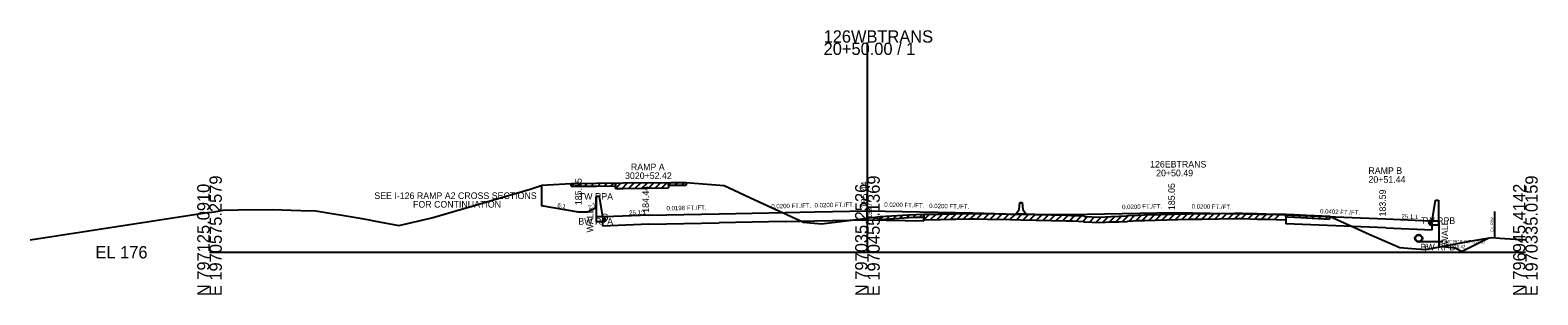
# Model space of a CAD drawing. Extents: x -6494 to 1970605, y -10 to 798140.
# Drawn here: x 959.1 to 1302.8, y 2990.3 to 3050.6 of the extents above; entities that cross this region are included whole.
import ezdxf

# ---------------------------------------------------------------- set-up
doc = ezdxf.new("R2010")
doc.units = 0
for name, color, linetype in [('Default', 7, 'Continuous'), ('RD_EX_SU_Misc_TxCode', 7, 'Continuous'), ('RD_GPK_XS_Cell', 7, 'Continuous'), ('RD_Sketch1', 7, 'Continuous'), ('RD_XS_Base', 7, 'Continuous'), ('RD_XS_Box', 7, 'Continuous'), ('RD_XS_EwShp', 7, 'Continuous'), ('RD_XS_ExGround', 7, 'Continuous'), ('RD_XS_ExPaveRet', 7, 'Continuous'), ('RD_XS_ExRW', 7, 'Continuous'), ('RD_XS_MedBWall', 7, 'Continuous'), ('RD_XS_Misc_Line', 7, 'Continuous'), ('RD_XS_Pave', 7, 'Continuous'), ('RD_XS_PaveOvlay', 7, 'Continuous'), ('RD_XS_PaveShd', 7, 'Continuous'), ('RD_XS_Pipe', 7, 'Continuous'), ('RD_XS_TieSlope', 7, 'Continuous'), ('RD_XS_TX_Elev_EX', 7, 'Continuous'), ('RD_XS_TX_Elev_PR', 7, 'Continuous'), ('RD_XS_TX_Misc', 7, 'Continuous'), ('RD_XS_TX_Notes', 7, 'Continuous'), ('RD_XS_TX_Profile', 7, 'Continuous'), ('RD_XS_TX_Slope', 7, 'Continuous'), ('RD_XS_TX_Station', 7, 'Continuous')]:
    doc.layers.add(name, color=color, linetype=linetype)

msp = doc.modelspace()

# ---------------------------------------------------------------- linework, layer by layer
at = {"layer": 'Default'}
for p, q in [((1184.58, 3009.76), (1184.75, 3011.34)), ((1184.75, 3011.34), (1185.25, 3011.34)), ((1185.25, 3011.34), (1185.42, 3009.76)), ((1184, 3008.92), (1184.58, 3009.76)), ((1184, 3008.67), (1184, 3008.92)), ((1186, 3008.67), (1184, 3008.67)), ((1185.42, 3009.76), (1186, 3008.92)), ((1186, 3008.92), (1186, 3008.67))]:
    msp.add_line(p, q, dxfattribs=at)
at = {"layer": 'RD_GPK_XS_Cell'}
for p, q in [((1150, 3000), (1150, 3047.74)), ((1000, 3000), (1150, 3000)), ((1150, 3000), (1300, 3000))]:
    msp.add_line(p, q, dxfattribs=at)
at = {"layer": 'RD_XS_Base'}
for p, q in [((1090.15, 3007.48), (1090.15, 3008.04)), ((1089.65, 3007.46), (1090.15, 3007.48)), ((1089.65, 3005.98), (1089.65, 3007.46)), ((1100.18, 3006.4), (1089.65, 3005.98)), ((1100.18, 3006.4), (1116.23, 3006.72)), ((1131.27, 3007.02), (1116.23, 3006.72)), ((1131.27, 3007.02), (1138, 3007.16)), ((1138, 3007.16), (1150, 3007.4)), ((1150, 3007.4), (1162.89, 3007.14)), ((1268.18, 3005.55), (1245.36, 3006.47)), ((1268.18, 3005.55), (1278.72, 3005.13)), ((1278.22, 3006.63), (1278.22, 3007.19)), ((1278.72, 3006.61), (1278.22, 3006.63)), ((1278.72, 3005.13), (1278.72, 3006.61))]:
    msp.add_line(p, q, dxfattribs=at)
at = {"layer": 'RD_XS_Box'}
for p, q in [((1088.15, 3010.22), (1088.15, 3008.04)), ((1090.15, 3008.04), (1088.15, 3008.04)), ((1278.22, 3007.19), (1280.23, 3007.19)), ((1280.23, 3007.19), (1280.23, 3001.18))]:
    msp.add_line(p, q, dxfattribs=at)
at = {"layer": 'RD_XS_ExGround'}
msp.add_line((1000, 3009.07), (959.11, 3002.75), dxfattribs=at)
msp.add_lwpolyline([(1000, 3009.07), (1001.06, 3009.23), (1003.09, 3009.6), (1006.52, 3009.65), (1014.26, 3009.73), (1020.8, 3009.53), (1024.25, 3009.42), (1033.88, 3007.83), (1036.39, 3007.39), (1037.48, 3007.18), (1043.18, 3006.13), (1050.69, 3007.85), (1073.12, 3014.35), (1075.82, 3015.3), (1077.09, 3015.37), (1082.48, 3015.65), (1084.28, 3015.67), (1088.23, 3015.7), (1094.32, 3015.78), (1105.19, 3015.91), (1107.73, 3015.91), (1108.67, 3015.91), (1110.58, 3015.75), (1117.31, 3015.18), (1124.29, 3011.97), (1135.39, 3006.86), (1137.03, 3006.7), (1139.5, 3006.48), (1150, 3007.77), (1150.38, 3007.82), (1152.88, 3008.11), (1159.39, 3008.52), (1161.11, 3008.62), (1166.64, 3008.71), (1169.08, 3008.75), (1170.16, 3008.78), (1173.1, 3008.86), (1174.57, 3008.84), (1177.35, 3008.79), (1182.55, 3008.7), (1184.98, 3008.65), (1195.28, 3008.44), (1196.46, 3008.41), (1196.79, 3008.4), (1199.26, 3008.28), (1199.49, 3008.18), (1202.92, 3008.03), (1205.59, 3008.15), (1207.4, 3008.21), (1209.15, 3008.27), (1209.45, 3008.35), (1211.78, 3008.45), (1213.18, 3008.49), (1223.34, 3008.77), (1226.24, 3008.81), (1230.18, 3008.85), (1233.77, 3008.92), (1234.87, 3008.94), (1235.5, 3008.92), (1238.91, 3008.81), (1240.93, 3008.76), (1247.31, 3008.62), (1250.09, 3008.48), (1255.36, 3008.19), (1264.38, 3004.1), (1271.37, 3001.05), (1274.01, 3000.84), (1277.2, 3000.61), (1285.34, 3002.15), (1286.96, 3002.46), (1290.46, 3003.04), (1292.29, 3003.33), (1294.2, 3003.2), (1300, 3002.8)], dxfattribs=at)
at = {"layer": 'RD_XS_ExPaveRet'}
for p, q in [((1082.48, 3015.02), (1082.48, 3015.65)), ((1082.48, 3015.02), (1084.28, 3015.04)), ((1084.28, 3015.04), (1088.23, 3015.08)), ((1088.23, 3015.08), (1092.54, 3015.13)), ((1092.54, 3014.51), (1092.54, 3015.76)), ((1092.54, 3015.76), (1092.54, 3015.13)), ((1094.32, 3014.53), (1104.65, 3014.66)), ((1104.65, 3015.91), (1104.65, 3014.66)), ((1104.65, 3015.28), (1104.65, 3015.91)), ((1104.65, 3015.28), (1105.19, 3015.29)), ((1105.19, 3015.29), (1107.73, 3015.28)), ((1107.73, 3015.28), (1108.67, 3015.28)), ((1108.67, 3015.91), (1108.67, 3015.28)), ((1092.54, 3014.51), (1094.32, 3014.53)), ((1152.88, 3007.49), (1152.88, 3008.11)), ((1152.88, 3007.49), (1159.39, 3007.89)), ((1159.39, 3007.89), (1161.11, 3008)), ((1161.11, 3008), (1162.89, 3008.03)), ((1162.89, 3007.4), (1162.89, 3008.65)), ((1162.89, 3008.65), (1162.89, 3008.03)), ((1230.18, 3007.6), (1233.77, 3007.67)), ((1233.77, 3007.67), (1234.87, 3007.69)), ((1234.87, 3007.69), (1235.5, 3007.67)), ((1235.5, 3007.67), (1238.91, 3007.56)), ((1245.36, 3008.66), (1245.36, 3007.41)), ((1245.36, 3008.04), (1245.36, 3008.66)), ((1245.36, 3008.04), (1247.31, 3007.99)), ((1247.31, 3007.99), (1250.09, 3007.85)), ((1250.09, 3007.85), (1255.36, 3007.57)), ((1255.36, 3008.19), (1255.36, 3007.57)), ((1162.89, 3007.4), (1166.64, 3007.46)), ((1166.64, 3007.46), (1169.08, 3007.5)), ((1169.08, 3007.5), (1170.16, 3007.53)), ((1170.16, 3007.53), (1173.1, 3007.61)), ((1173.1, 3007.61), (1174.57, 3007.59)), ((1174.57, 3007.59), (1177.35, 3007.54)), ((1177.35, 3007.54), (1182.55, 3007.45)), ((1182.55, 3007.45), (1184.98, 3007.4)), ((1184.98, 3007.4), (1195.28, 3007.19)), ((1195.28, 3007.19), (1196.46, 3007.16)), ((1196.46, 3007.16), (1196.79, 3007.15)), ((1196.79, 3007.15), (1199.26, 3007.03)), ((1199.26, 3007.03), (1199.49, 3006.93)), ((1199.49, 3006.93), (1202.92, 3006.78)), ((1202.92, 3006.78), (1205.59, 3006.9)), ((1205.59, 3006.9), (1207.4, 3006.96)), ((1207.4, 3006.96), (1209.15, 3007.02)), ((1209.15, 3007.02), (1209.45, 3007.1)), ((1209.45, 3007.1), (1211.78, 3007.2)), ((1211.78, 3007.2), (1213.18, 3007.24)), ((1213.18, 3007.24), (1223.34, 3007.52)), ((1223.34, 3007.52), (1226.24, 3007.56)), ((1226.24, 3007.56), (1230.18, 3007.6)), ((1238.91, 3007.56), (1240.93, 3007.51)), ((1240.93, 3007.51), (1245.36, 3007.41))]:
    msp.add_line(p, q, dxfattribs=at)
at = {"layer": 'RD_XS_ExRW'}
msp.add_line((1292.97, 3009.29), (1292.97, 3003.29), dxfattribs=at)
at = {"layer": 'RD_XS_MedBWall'}
for p, q in [((1088.9, 3012.71), (1088.15, 3012.71)), ((1088.15, 3012.71), (1088.15, 3007.04)), ((1088.15, 3010.22), (1088.15, 3012.71)), ((1089.65, 3008.04), (1088.9, 3012.71)), ((1278.72, 3007.19), (1279.47, 3011.85)), ((1279.47, 3011.85), (1280.22, 3011.85)), ((1280.22, 3011.85), (1280.22, 3006.19)), ((1090.15, 3008.04), (1089.65, 3008.04)), ((1090.15, 3007.04), (1090.15, 3008.04)), ((1088.15, 3007.04), (1090.15, 3007.04)), ((1278.22, 3006.19), (1278.22, 3007.19)), ((1278.22, 3007.19), (1278.72, 3007.19)), ((1280.22, 3006.19), (1278.22, 3006.19))]:
    msp.add_line(p, q, dxfattribs=at)
at = {"layer": 'RD_XS_Misc_Line'}
for p, q in [((1082.48, 3015.02), (1083.12, 3015.65)), ((1083.99, 3015.04), (1084.63, 3015.67)), ((1085.5, 3015.05), (1086.13, 3015.68)), ((1087.01, 3015.07), (1087.64, 3015.7)), ((1088.52, 3015.08), (1089.15, 3015.71)), ((1090.02, 3015.1), (1090.66, 3015.73)), ((1091.53, 3015.12), (1092.17, 3015.75)), ((1092.54, 3014.51), (1093.81, 3015.77)), ((1094.05, 3014.52), (1095.32, 3015.79)), ((1095.55, 3014.54), (1096.83, 3015.81)), ((1097.06, 3014.56), (1098.34, 3015.83)), ((1098.57, 3014.58), (1099.84, 3015.85)), ((1100.08, 3014.6), (1101.35, 3015.87)), ((1101.59, 3014.62), (1102.86, 3015.88)), ((1103.1, 3014.64), (1104.37, 3015.9)), ((1104.65, 3015.28), (1105.28, 3015.91)), ((1106.16, 3015.29), (1106.78, 3015.91)), ((1107.67, 3015.28), (1108.29, 3015.91)), ((1152.88, 3007.49), (1153.56, 3008.15)), ((1154.39, 3007.58), (1155.06, 3008.25)), ((1155.9, 3007.67), (1156.57, 3008.34)), ((1157.41, 3007.77), (1158.08, 3008.43)), ((1158.92, 3007.86), (1159.59, 3008.53)), ((1160.43, 3007.95), (1161.09, 3008.62)), ((1161.93, 3008.01), (1162.57, 3008.65)), ((1162.89, 3007.4), (1164.16, 3008.67)), ((1164.39, 3007.43), (1165.67, 3008.7)), ((1165.9, 3007.45), (1167.18, 3008.72)), ((1167.41, 3007.48), (1168.69, 3008.75)), ((1168.92, 3007.5), (1170.21, 3008.78)), ((1170.43, 3007.54), (1171.72, 3008.82)), ((1171.93, 3007.58), (1173.22, 3008.86)), ((1173.44, 3007.6), (1174.68, 3008.84)), ((1174.95, 3007.58), (1176.19, 3008.81)), ((1176.46, 3007.56), (1177.69, 3008.78)), ((1177.97, 3007.53), (1179.2, 3008.76)), ((1179.48, 3007.5), (1180.71, 3008.73)), ((1180.98, 3007.48), (1182.22, 3008.71)), ((1182.49, 3007.45), (1183.72, 3008.68)), ((1184, 3007.42), (1185.23, 3008.65)), ((1185.51, 3007.39), (1186.74, 3008.62)), ((1187.02, 3007.36), (1188.25, 3008.58)), ((1188.52, 3007.33), (1189.76, 3008.55)), ((1190.03, 3007.3), (1191.26, 3008.52)), ((1191.54, 3007.27), (1192.77, 3008.49)), ((1193.05, 3007.23), (1194.28, 3008.46)), ((1194.56, 3007.2), (1195.79, 3008.43)), ((1196.07, 3007.17), (1197.28, 3008.37)), ((1197.57, 3007.11), (1198.77, 3008.3)), ((1199.08, 3007.03), (1200.2, 3008.15)), ((1200.59, 3006.88), (1201.79, 3008.08)), ((1202.1, 3006.81), (1203.34, 3008.04)), ((1203.61, 3006.81), (1204.92, 3008.12)), ((1205.11, 3006.88), (1206.42, 3008.18)), ((1206.62, 3006.93), (1207.92, 3008.23)), ((1208.13, 3006.98), (1209.51, 3008.36)), ((1209.64, 3007.11), (1210.95, 3008.42)), ((1211.15, 3007.17), (1212.45, 3008.47)), ((1212.66, 3007.23), (1213.95, 3008.51)), ((1214.16, 3007.27), (1215.46, 3008.55)), ((1215.67, 3007.31), (1216.97, 3008.6)), ((1217.18, 3007.35), (1218.47, 3008.64)), ((1218.69, 3007.39), (1219.98, 3008.68)), ((1220.2, 3007.44), (1221.49, 3008.72)), ((1221.7, 3007.48), (1223, 3008.76)), ((1223.21, 3007.52), (1224.49, 3008.79)), ((1224.72, 3007.54), (1226, 3008.81)), ((1226.23, 3007.56), (1227.5, 3008.83)), ((1227.74, 3007.58), (1229.01, 3008.84)), ((1229.25, 3007.59), (1230.52, 3008.86)), ((1230.75, 3007.61), (1232.04, 3008.89)), ((1232.26, 3007.64), (1233.54, 3008.92)), ((1233.77, 3007.67), (1235.04, 3008.94)), ((1235.28, 3007.68), (1236.5, 3008.89)), ((1236.79, 3007.63), (1238.01, 3008.84)), ((1238.3, 3007.58), (1239.52, 3008.8)), ((1239.8, 3007.54), (1241.03, 3008.76)), ((1241.31, 3007.51), (1242.54, 3008.73)), ((1242.82, 3007.47), (1244.05, 3008.69)), ((1245.36, 3008.04), (1245.97, 3008.65)), ((1246.87, 3008), (1247.48, 3008.61)), ((1248.37, 3007.94), (1248.97, 3008.53)), ((1249.88, 3007.86), (1250.48, 3008.46)), ((1251.39, 3007.78), (1251.99, 3008.38)), ((1252.9, 3007.7), (1253.5, 3008.29)), ((1254.41, 3007.62), (1255, 3008.21))]:
    msp.add_line(p, q, dxfattribs=at)
at = {"layer": 'RD_XS_Pave'}
for p, q in [((1100.18, 3008.44), (1116.23, 3008.76)), ((1131.27, 3009.06), (1138, 3009.2)), ((1138, 3009.2), (1150, 3009.44)), ((1150, 3009.44), (1174, 3008.96)), ((1196.09, 3008.57), (1220.09, 3009.05)), ((1220.09, 3009.05), (1232.09, 3008.81)), ((1232.09, 3008.81), (1243.24, 3008.59)), ((1243.24, 3008.59), (1268.18, 3007.59))]:
    msp.add_line(p, q, dxfattribs=at)
at = {"layer": 'RD_XS_PaveOvlay'}
for p, q in [((1162.89, 3008.65), (1166.64, 3008.71)), ((1162.89, 3008.65), (1162.89, 3007.14)), ((1166.64, 3008.71), (1169.08, 3008.75)), ((1169.08, 3008.75), (1170.16, 3008.78)), ((1170.16, 3008.78), (1173.1, 3008.86)), ((1173.1, 3008.86), (1174.57, 3008.84)), ((1174.57, 3008.84), (1177.35, 3008.79)), ((1177.35, 3008.79), (1182.55, 3008.7)), ((1182.55, 3008.7), (1184.98, 3008.65)), ((1184.98, 3008.65), (1195.28, 3008.44)), ((1195.28, 3008.44), (1196.46, 3008.41)), ((1196.46, 3008.41), (1196.79, 3008.4)), ((1196.79, 3008.4), (1199.26, 3008.28)), ((1199.26, 3008.28), (1199.49, 3008.18)), ((1199.49, 3008.18), (1202.92, 3008.03)), ((1202.92, 3008.03), (1205.59, 3008.15)), ((1205.59, 3008.15), (1207.4, 3008.21)), ((1207.4, 3008.21), (1209.15, 3008.27)), ((1209.15, 3008.27), (1209.45, 3008.35)), ((1209.45, 3008.35), (1211.78, 3008.45)), ((1211.78, 3008.45), (1213.18, 3008.49)), ((1213.18, 3008.49), (1223.34, 3008.77)), ((1223.34, 3008.77), (1226.24, 3008.81)), ((1226.24, 3008.81), (1230.18, 3008.85)), ((1230.18, 3008.85), (1233.77, 3008.92)), ((1233.77, 3008.92), (1234.87, 3008.94)), ((1234.87, 3008.94), (1235.5, 3008.92)), ((1235.5, 3008.92), (1238.91, 3008.81)), ((1238.91, 3008.81), (1240.93, 3008.76)), ((1240.93, 3008.76), (1245.36, 3008.66)), ((1245.36, 3008.66), (1245.36, 3006.47))]:
    msp.add_line(p, q, dxfattribs=at)
at = {"layer": 'RD_XS_PaveShd'}
for p, q in [((1100.18, 3008.44), (1090.15, 3008.04)), ((1116.23, 3008.76), (1131.27, 3009.06)), ((1174, 3008.96), (1184, 3008.67)), ((1192.35, 3008.5), (1184, 3008.67)), ((1196.09, 3008.57), (1192.35, 3008.5)), ((1268.18, 3007.59), (1278.22, 3007.19))]:
    msp.add_line(p, q, dxfattribs=at)
at = {"layer": 'RD_XS_Pipe'}
msp.add_line((1276.17, 3002.42), (1281.17, 3002.42), dxfattribs=at)
for radius in [0.85, 0.75]:
    msp.add_circle((1275.67, 3003.17), radius, dxfattribs=at)
at = {"layer": 'RD_XS_TieSlope'}
for p, q in [((1075.69, 3015.26), (1075.69, 3010.56)), ((1084.15, 3009.15), (1075.69, 3010.56)), ((1086.15, 3009.15), (1084.15, 3009.15)), ((1088.15, 3010.15), (1086.15, 3009.15)), ((1280.23, 3001.38), (1284, 3001.01)), ((1284, 3001.01), (1285.62, 3000.2)), ((1291.69, 3003.24), (1285.62, 3000.2))]:
    msp.add_line(p, q, dxfattribs=at)

# ---------------------------------------------------------------- texts
at = {"layer": 'RD_EX_SU_Misc_TxCode'}
msp.add_text('G', height=1.5, dxfattribs=at).set_placement((1089.4, 3007.29))
at = {"layer": 'RD_GPK_XS_Cell'}
for s, p in [('126WBTRANS', (1140, 3047.74)), ('20+50.00 / 1', (1140, 3044.94)), ('EL 176', (974, 2998.6))]:
    msp.add_text(s, height=2.8, dxfattribs=at).set_placement(p)
for s, p in [('N 797125.0910', (1000, 2990)), ('E 1970575.2579', (1002.8, 2990)), ('N 797035.2526', (1150, 2990)), ('E 1970455.1369', (1152.8, 2990)), ('N 796945.4142', (1300, 2990)), ('E 1970335.0159', (1302.8, 2990))]:
    msp.add_text(s, height=2.8, rotation=90, dxfattribs=at).set_placement(p)
at = {"layer": 'RD_Sketch1'}
msp.add_text('T', height=1.5, dxfattribs=at).set_placement((1276.65, 2999.86))
at = {"layer": 'RD_XS_EwShp'}
for s, p in [('TW RPA', (1084.19, 3011.96)), ('BW RPA', (1084.09, 3006.29)), ('TW RPB', (1276.2, 3006.44)), ('BW RPB', (1276.1, 3000.43))]:
    msp.add_text(s, height=1.5, dxfattribs=at).set_placement(p)
at = {"layer": 'RD_XS_ExRW'}
msp.add_text('Ex. R/W ', height=0.65, rotation=90, dxfattribs=at).set_placement((1292.72, 3004.67))
at = {"layer": 'RD_XS_Pipe'}
for s, p in [('18" RCP (NP-1793)', (1281.67, 3002.04)), ('FL 178.42', (1281.67, 3000.92))]:
    msp.add_text(s, height=0.75, dxfattribs=at).set_placement(p)
at = {"layer": 'RD_XS_TX_Elev_EX'}
msp.add_text('183.77', height=1, rotation=90, dxfattribs=at).set_placement((1151, 3007.77))
at = {"layer": 'RD_XS_TX_Elev_PR'}
for s, p in [(' 184.44', (1100.18, 3008.44)), (' 185.44', (1150, 3009.44)), (' 185.05', (1220.09, 3009.05)), (' 183.59', (1268.18, 3007.59))]:
    msp.add_text(s, height=1.5, rotation=90, dxfattribs=at).set_placement(p)
at = {"layer": 'RD_XS_TX_Misc'}
msp.add_text('185.15', height=1.5, rotation=90, dxfattribs=at).set_placement((1084.85, 3010.73))
at = {"layer": 'RD_XS_TX_Notes'}
for s, p in [('SEE I-126 RAMP A2 CROSS SECTIONS', (1037.58, 3012.13)), ('FOR CONTINUATION', (1046.4, 3010.16))]:
    msp.add_text(s, height=1.5, dxfattribs=at).set_placement(p)
for p in [(1087.48, 3004.51), (1282.39, 3001.79)]:
    msp.add_text('WALL', height=1.5, rotation=90, dxfattribs=at).set_placement(p)
at = {"layer": 'RD_XS_TX_Profile'}
msp.add_text('25.1:1', height=1, rotation=357.7183, dxfattribs=at).set_placement((1271.73, 3007.7))
at = {"layer": 'RD_XS_TX_Slope'}
for s, rotation, p in [('6:1', 350.5377, (1079.25, 3010.27)), ('2:1', 26.5651, (1086.55, 3009.66)), ('0.0200 FT./FT.', 1.1458, (1128.09, 3009.97)), ('0.0200 FT./FT.', 1.1432, (1137.95, 3010.2)), ('0.0200 FT./FT.', 358.8542, (1153.83, 3010.36)), ('25.1:1', 2.2838, (1095.68, 3008.51)), ('0.0198 FT./FT.', 1.1337, (1104.2, 3009.52)), ('0.0200 FT./FT.', 358.8542, (1164.07, 3010.08)), ('0.0200 FT./FT.', 1.1455, (1208.07, 3009.81)), ('0.0200 FT./FT.', 358.854, (1223.91, 3009.98)), ('0.0402 FT./FT.', 357.6999, (1253.18, 3008.87))]:
    msp.add_text(s, height=1, rotation=rotation, dxfattribs=at).set_placement(p)
at = {"layer": 'RD_XS_TX_Station'}
for s, p in [('3020+52.42', (1094.73, 3016.69)), ('RAMP A', (1096.07, 3018.69)), ('126EBTRANS', (1214.44, 3019.3)), ('20+50.49', (1215.82, 3017.3)), ('RAMP B', (1264.21, 3017.84)), ('20+51.44', (1264.23, 3015.84))]:
    msp.add_text(s, height=1.5, dxfattribs=at).set_placement(p)

doc.saveas('drawing.dxf')
